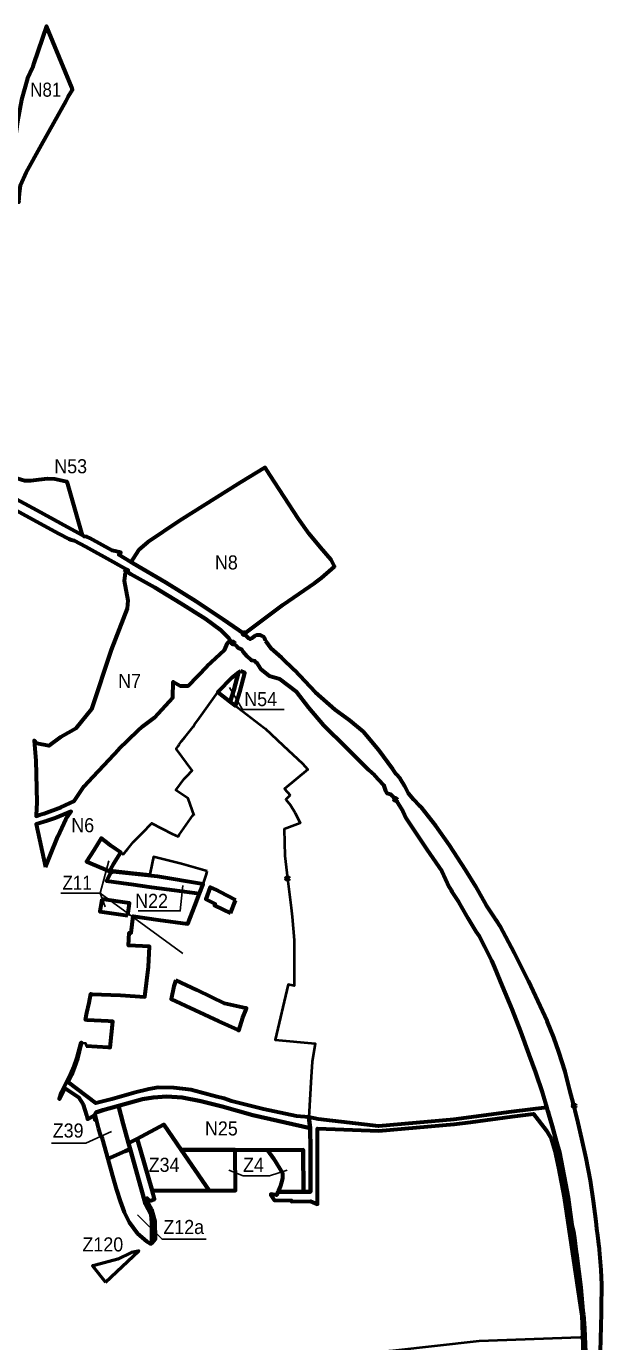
# Model space of a CAD drawing. Extents: x -650277 to -643425, y -1073980 to -1066720.
# Drawn here: x -645952 to -644970, y -1070373 to -1068130 of the extents above; entities that cross this region are included whole.
import ezdxf

# ---------------------------------------------------------------- set-up
doc = ezdxf.new("R2010")
doc.units = 0
doc.header["$LTSCALE"] = 9.6
doc.header["$PDMODE"] = 32
doc.header["$PDSIZE"] = 4.8
for name, color, linetype, lineweight in [('1', 7, 'Continuous', 60), ('11', 7, 'Continuous', 60), ('15', 7, 'Continuous', 60), ('2', 7, 'Continuous', 40), ('3', 7, 'Continuous', 60), ('40', 7, 'Continuous', 60), ('42', 7, 'Continuous', 60), ('48', 7, 'Continuous', 60), ('60', 7, 'Continuous', 60), ('63', 7, 'Continuous', 25), ('7', 7, 'Continuous', 60)]:
    doc.layers.add(name, color=color, linetype=linetype, lineweight=lineweight)

msp = doc.modelspace()

# ---------------------------------------------------------------- linework, layer by layer
at = {"layer": '1'}
msp.add_line((-645623.75, -1069825.97), (-645590.964, -1069841.09), dxfattribs=at)
at = {"layer": '1', "lineweight": 40}
msp.add_line((-645726.542, -1069939.398), (-645742.967, -1069941.862), dxfattribs=at)
for points in [[(-645668.722, -1069398.75), (-645696.19, -1069362.01), (-645692.38, -1069356.67), (-645690.81, -1069354.28), (-645687.22, -1069349), (-645680.8, -1069341.08), (-645667, -1069324.06), (-645664.89, -1069320.2), (-645658.9, -1069312.83), (-645625.11, -1069265.42), (-645604.114, -1069281.49), (-645594.94, -1069288.511)], [(-645594.94, -1069288.511), (-645583.13, -1069297.55), (-645546.19, -1069325.81), (-645544.26, -1069327.35), (-645513.41, -1069356.18), (-645480.72, -1069386.96), (-645471.738, -1069397.026), (-645511.464, -1069429.794), (-645501.878, -1069440.838)], [(-645665.58, -1069475.61), (-645675.91, -1069446.56), (-645696.45, -1069432.21), (-645682.28, -1069412.88), (-645678.06, -1069408.54), (-645668.61, -1069398.9), (-645668.722, -1069398.75)], [(-645501.878, -1069440.838), (-645508.994, -1069447.955), (-645501, -1069458), (-645493, -1069471), (-645484.783, -1069488.256), (-645512, -1069499), (-645511, -1069544), (-645506, -1069583)], [(-645786.388, -1069541.673), (-645779.376, -1069532.962), (-645778.754, -1069532.198), (-645769.369, -1069520.672), (-645768.995, -1069520.305), (-645752.715, -1069504.328), (-645738.986, -1069489.868), (-645737.897, -1069488.534), (-645702.82, -1069506.64), (-645692.87, -1069511.229), (-645690.84, -1069508.32), (-645667.31, -1069474.6), (-645665.58, -1069475.61)], [(-645836.44, -1069534.5), (-645824.05, -1069514.34), (-645811.75, -1069523.81), (-645808.1, -1069526.61), (-645799.07, -1069532.8), (-645790.62, -1069538.59), (-645786.388, -1069541.673)], [(-645810.08, -1069570.39), (-645848.78, -1069553.91), (-645836.44, -1069534.5)], [(-645643.16, -1069570.6), (-645687.29, -1069558.04), (-645734.5, -1069545.89), (-645736.8, -1069556.91), (-645741.14, -1069576.19), (-645769.04, -1069573), (-645803.513, -1069569.263), (-645810.08, -1069570.39)], [(-645676.34, -1069660.28), (-645670.23, -1069644.67), (-645664.19, -1069629.24), (-645657.52, -1069612.2), (-645656.15, -1069608.71), (-645649.91, -1069592.39), (-645648.68, -1069589.06), (-645644.56, -1069575.61), (-645643.16, -1069570.6)], [(-645506, -1069583), (-645500.137, -1069632.833), (-645500.137, -1069632.833)], [(-645500.137, -1069632.833), (-645498, -1069648), (-645495, -1069688), (-645495, -1069744), (-645495, -1069766), (-645504.976, -1069763.332), (-645527, -1069858), (-645459.312, -1069864.01), (-645464.288, -1069895.362), (-645465.756, -1069921.035), (-645469.701, -1069990.011)], [(-645839.721, -1069780.247), (-645839.658, -1069779.835), (-645791.2, -1069781.92), (-645749.48, -1069784.61), (-645743.36, -1069733.7), (-645743.01, -1069730.72), (-645741.43, -1069698.68), (-645763.24, -1069697.58), (-645777.62, -1069696.85), (-645776.45, -1069675.26), (-645773.02, -1069675.47), (-645769.36, -1069648), (-645769.264, -1069647.213), (-645726.57, -1069653.22), (-645676.34, -1069660.28)], [(-645804.185, -1069825.84), (-645804.28, -1069826.76), (-645812.18, -1069826.3), (-645847.62, -1069824.26), (-645850.63, -1069824.09), (-645848.35, -1069812.09), (-645844.57, -1069795.07), (-645841.41, -1069779.76), (-645839.658, -1069779.835), (-645839.721, -1069780.247)], [(-645742.967, -1069941.862), (-645768.424, -1069948.431), (-645833, -1069966), (-645880.431, -1069930.3), (-645874.219, -1069917.496), (-645869.262, -1069905.935), (-645863.95, -1069889.468), (-645857.289, -1069863.338), (-645857.204, -1069862.954), (-645850.92, -1069863.41), (-645849.79, -1069868.4), (-645808.84, -1069870.75), (-645808.28, -1069865.39), (-645804.185, -1069825.84)], [(-645469.701, -1069990.011), (-645490.814, -1069988.074), (-645547.4, -1069976.382), (-645614.072, -1069957.797), (-645625.979, -1069954.92), (-645670.325, -1069943.002), (-645699.889, -1069939.714), (-645726.542, -1069939.398)]]:
    msp.add_lwpolyline(points, dxfattribs=at)
at = {"layer": '1'}
for points in [[(-645836.44, -1069534.5), (-645848.78, -1069553.91), (-645810.08, -1069570.39), (-645803.07, -1069558.62), (-645790.62, -1069538.59), (-645799.07, -1069532.8), (-645808.1, -1069526.61), (-645811.75, -1069523.81), (-645824.05, -1069514.34)], [(-645639.638, -1070114.895), (-645594.733, -1070114.868), (-645595.2, -1070045.403), (-645687.31, -1070045.724)], [(-645522.587, -1070116.952), (-645478.664, -1070117.114), (-645479.429, -1070045.409), (-645540.433, -1070045.752), (-645530.3, -1070060.08), (-645514.49, -1070085.4), (-645514.56, -1070090.91), (-645514.61, -1070094.35), (-645517.02, -1070103.08), (-645518.35, -1070106.87), (-645521.73, -1070114.83)]]:
    msp.add_lwpolyline(points, close=True, dxfattribs=at)
for points in [[(-645849.79, -1069868.4), (-645811.848, -1069870.577), (-645808.84, -1069870.75), (-645804.28, -1069826.76), (-645812.18, -1069826.3), (-645847.62, -1069824.26), (-645850.63, -1069824.09), (-645848.35, -1069812.09), (-645844.57, -1069795.07), (-645841.41, -1069779.76), (-645839.658, -1069779.835), (-645791.2, -1069781.92), (-645749.48, -1069784.61), (-645743.36, -1069733.7), (-645741.43, -1069698.68), (-645777.62, -1069696.85), (-645776.45, -1069675.26), (-645773.02, -1069675.47), (-645769.264, -1069647.213), (-645726.57, -1069653.22), (-645676.34, -1069660.28), (-645664.19, -1069629.24), (-645656.15, -1069608.71)], [(-645594.58, -1069619.56), (-645621.56, -1069605.68), (-645626.95, -1069602.91), (-645638.203, -1069597.8), (-645645.715, -1069618.085), (-645629.78, -1069626.03), (-645630.93, -1069628.84), (-645603.7, -1069641.75)], [(-645823.082, -1069618.279), (-645823.13, -1069618.452), (-645825.295, -1069632.053), (-645826.133, -1069638.843), (-645826.151, -1069639.057), (-645778.45, -1069645.92)], [(-645778.45, -1069645.92), (-645775.46, -1069625.13), (-645823.082, -1069618.279)], [(-645603.7, -1069641.75), (-645594.818, -1069620.139), (-645594.58, -1069619.56)], [(-645696.517, -1069756.039), (-645700.028, -1069766.286), (-645704.355, -1069788.786), (-645623.75, -1069825.97)], [(-645578.134, -1069803.73), (-645613.84, -1069795.78), (-645635.79, -1069785.23), (-645660.57, -1069773.31), (-645696.517, -1069756.039)], [(-645590.964, -1069841.09), (-645589.23, -1069841.89), (-645582.31, -1069820.05), (-645577.52, -1069807.26), (-645576.34, -1069804.13), (-645578.134, -1069803.73)], [(-645772.853, -1070049.868), (-645774.423, -1070044.167), (-645783.063, -1070047.855), (-645812.76, -1070060.53)], [(-645737.756, -1070204.389), (-645737.624, -1070169.544), (-645738.79, -1070156.281), (-645748.62, -1070137.889), (-645772.853, -1070049.868)], [(-645812.76, -1070060.53), (-645804.52, -1070089.63), (-645797.66, -1070113.88), (-645791.72, -1070133.09), (-645784.83, -1070151.9), (-645784.83, -1070151.9)], [(-645784.83, -1070151.9), (-645776.26, -1070168.94), (-645761.78, -1070188.29), (-645746.73, -1070201.04), (-645739.12, -1070205.9), (-645737.756, -1070204.389)]]:
    msp.add_lwpolyline(points, dxfattribs=at)
at = {"layer": '1', "lineweight": 53}
msp.add_lwpolyline([(-645816.9, -1070270.96), (-645760.05, -1070217.79), (-645760.91, -1070217.98), (-645772.08, -1070220.39), (-645795.85, -1070231.81), (-645833.92, -1070241.96), (-645838.53, -1070243.19)], close=True, dxfattribs=at)
at = {"layer": '1'}
msp.add_point((-645506, -1069583), dxfattribs=at)
at = {"layer": '11'}
msp.add_lwpolyline([(-645639.638, -1070114.895), (-645687.31, -1070045.724), (-645717.36, -1070002.12), (-645762.868, -1070026.606), (-645757.215, -1070045.97), (-645737.075, -1070114.955)], close=True, dxfattribs=at)
at = {"layer": '15'}
for points in [[(-645586.39, -1069229.32), (-645589.844, -1069231.908), (-645597.738, -1069261.522), (-645604.114, -1069281.49), (-645594.94, -1069288.511), (-645587.298, -1069264.578), (-645578.713, -1069232.375)], [(-645735.532, -1069956.306), (-645712.222, -1069954.725), (-645686.147, -1069956.306), (-645654.145, -1069962.232), (-645617.403, -1069971.714), (-645565.133, -1069986.508), (-645467.472, -1070008.38), (-645469.701, -1069990.011), (-645490.814, -1069988.074), (-645547.4, -1069976.382), (-645601.753, -1069962.317), (-645614.072, -1069957.797), (-645625.979, -1069954.92), (-645670.325, -1069943.002), (-645699.889, -1069939.714), (-645726.542, -1069939.398), (-645742.967, -1069941.862), (-645768.424, -1069948.431), (-645806, -1069959), (-645833, -1069966), (-645880.431, -1069930.3), (-645874.219, -1069917.496), (-645869.262, -1069905.935), (-645863.95, -1069889.468), (-645857.289, -1069863.338), (-645857.204, -1069862.954), (-645858.78, -1069862.84), (-645865.78, -1069888.76), (-645870.89, -1069903.5), (-645876.15, -1069916.47), (-645892.09, -1069947.98), (-645895.66, -1069958.42), (-645894.25, -1069958.7), (-645885.422, -1069940.184), (-645862.782, -1069955.809), (-645854.81, -1069967.927), (-645849.1, -1069986.42), (-645847.135, -1069993.337), (-645836.64, -1069987.18), (-645834.65, -1069994.21), (-645833.32, -1069991.86), (-645835, -1069985), (-645833, -1069982), (-645821, -1069978), (-645794.679, -1069970.596), (-645753.706, -1069959.071)]]:
    msp.add_lwpolyline(points, close=True, dxfattribs=at)
for points in [[(-645061.76, -1069981.21), (-645064.052, -1069973.429), (-645124.233, -1069980.695), (-645222.809, -1069993.701), (-645350.784, -1070005.227), (-645453.852, -1069992.968), (-645469.701, -1069990.011), (-645467.472, -1070008.38), (-645467.068, -1070044.959), (-645466.96, -1070117.157), (-645478.664, -1070117.114), (-645522.587, -1070116.952), (-645524.82, -1070122.48), (-645534.63, -1070121.09), (-645534.7, -1070122.95), (-645529.17, -1070131.4), (-645499.276, -1070131.652), (-645499.142, -1070133.293), (-645466.862, -1070133.219), (-645454.881, -1070137.836), (-645455.073, -1070009.111), (-645350.591, -1070013.242), (-645221.99, -1070001.66), (-645194.003, -1069998.417), (-645123.206, -1069988.629), (-645086.484, -1069984.195), (-645065.235, -1070011.695)], [(-644997.87, -1070391.16), (-644999.47, -1070349.63), (-645001.64, -1070326.4), (-645001.81, -1070324.58), (-645002.308, -1070319.268), (-645005.98, -1070280.14), (-645013.51, -1070222.04), (-645013.77, -1070220.04), (-645016.92, -1070196.32), (-645018.56, -1070184.92), (-645021.14, -1070173.07), (-645027.49, -1070126.56), (-645032.21, -1070102.73), (-645042.27, -1070049.23), (-645047.28, -1070031.83), (-645054.73, -1070004.56), (-645060.612, -1069985.022), (-645061.76, -1069981.21)], [(-645065.235, -1070011.695), (-645056.555, -1070026.163), (-645050.293, -1070047.035), (-645043.92, -1070076.344), (-645034.122, -1070126.616), (-645004.791, -1070324.889), (-645004.523, -1070326.697)], [(-645757.215, -1070045.97), (-645762.868, -1070026.606), (-645777.143, -1070034.287), (-645772.853, -1070049.868), (-645748.62, -1070137.889)], [(-645737.63, -1070147.39), (-645747.67, -1070129.14), (-645745.29, -1070127.83), (-645744.73, -1070129), (-645743.87, -1070130.15), (-645742.67, -1070131.07), (-645741.83, -1070131.53), (-645740.89, -1070131.8), (-645739.41, -1070131.93), (-645738.41, -1070131.78), (-645737.48, -1070131.45), (-645734.77, -1070130.18), (-645732.91, -1070129.5), (-645737.075, -1070114.955), (-645757.215, -1070045.97)], [(-645748.62, -1070137.889), (-645738.79, -1070156.281), (-645737.624, -1070169.544), (-645737.756, -1070204.389)], [(-645737.756, -1070204.389), (-645731.3, -1070197.24), (-645731.94, -1070167.87), (-645737.63, -1070147.39)], [(-645004.523, -1070326.697), (-645004.434, -1070327.302), (-645001.312, -1070412.099), (-645004.327, -1070461.264), (-645014.277, -1070543.11), (-645023.048, -1070595.033), (-645039.574, -1070675.065)]]:
    msp.add_lwpolyline(points, dxfattribs=at)
at = {"layer": '2'}
msp.add_lwpolyline([(-645023.048, -1070595.033), (-645014.277, -1070543.11), (-645004.327, -1070461.264), (-645001.312, -1070412.099), (-645003.03, -1070365.427), (-645003.102, -1070365.432), (-645006.86, -1070365.38), (-645179.26, -1070371.74), (-645326.62, -1070388.32), (-645414.65, -1070395.37), (-645409.38, -1070411.41), (-645408.66, -1070414.62), (-645404.34, -1070433.93), (-645404.4, -1070435.88), (-645440.61, -1070469.53), (-645451.226, -1070466.394), (-645455.09, -1070479.21), (-645458.46, -1070478.86), (-645454.02, -1070501.52), (-645448.36, -1070563), (-645449.82, -1070592.72), (-645442.834, -1070659.455)], dxfattribs=at)
at = {"layer": '3'}
for points in [[(-645794.679, -1069970.596), (-645821, -1069978), (-645833, -1069982), (-645835, -1069985), (-645833.32, -1069991.86)], [(-645833.32, -1069991.86), (-645828.9, -1070007.76), (-645825.08, -1070021.52)], [(-645777.143, -1070034.287), (-645786.238, -1070001.251), (-645794.679, -1069970.596)], [(-645825.08, -1070021.52), (-645823.76, -1070021.67), (-645822.549, -1070025.948), (-645812.76, -1070060.53), (-645783.063, -1070047.855), (-645774.423, -1070044.167), (-645777.143, -1070034.287)]]:
    msp.add_lwpolyline(points, dxfattribs=at)
at = {"layer": '40'}
for points in [[(-645698.83, -1069602.85), (-645656.15, -1069608.71), (-645649.91, -1069592.39), (-645727.71, -1069579.61), (-645803.33, -1069571.62), (-645808.18, -1069573.7), (-645814.82, -1069586.81), (-645777.26, -1069592.07), (-645772.58, -1069592.73), (-645738.13, -1069597.46)], [(-645595.2, -1070045.403), (-645479.429, -1070045.409), (-645478.664, -1070117.114), (-645466.96, -1070117.157), (-645467.068, -1070044.959), (-645467.472, -1070008.38), (-645565.133, -1069986.508), (-645617.403, -1069971.714), (-645654.145, -1069962.232), (-645686.147, -1069956.306), (-645712.222, -1069954.725), (-645735.532, -1069956.306), (-645753.706, -1069959.071), (-645794.679, -1069970.596), (-645786.238, -1070001.251), (-645777.143, -1070034.287), (-645762.868, -1070026.606), (-645717.36, -1070002.12), (-645687.31, -1070045.724)]]:
    msp.add_lwpolyline(points, close=True, dxfattribs=at)
at = {"layer": '42'}
for points in [[(-645856.26, -1068997.79), (-645892.77, -1068977.86), (-645933.28, -1068955.74), (-645975.31, -1068932.8), (-646017.55, -1068909.75)], [(-645973.36, -1068898.93), (-645954.59, -1068904.41), (-645944.23, -1068904.13), (-645930.1, -1068902.47), (-645915.61, -1068901.02), (-645902.91, -1068901.43), (-645882.63, -1068905.88), (-645856.26, -1068997.79)]]:
    msp.add_lwpolyline(points, dxfattribs=at)
msp.add_lwpolyline([(-645604.114, -1069281.49), (-645597.738, -1069261.522), (-645589.844, -1069231.908), (-645600.55, -1069239.93), (-645625.11, -1069265.42)], close=True, dxfattribs=at)
at = {"layer": '48'}
msp.add_lwpolyline([(-645874.15, -1068234.44), (-645917.44, -1068129.99), (-645938.87, -1068193.06), (-645941.41, -1068200.54), (-645949.52, -1068218.72), (-645959.76, -1068255.23), (-645966.56, -1068292.38), (-645973.25, -1068342.08), (-645976.63, -1068393.14), (-645971.94, -1068405.38), (-645964.53, -1068429.83), (-645963.12, -1068415.21), (-645961.7, -1068400.54), (-645952.21, -1068378.95), (-645926.06, -1068332.18), (-645883.87, -1068256.88), (-645880.28, -1068250.47), (-645872.64, -1068238.08)], close=True, dxfattribs=at)
at = {"layer": '60'}
for points in [[(-645579.94, -1069165.52), (-645616.63, -1069140.8), (-645662.44, -1069109.89), (-645713.61, -1069078.06), (-645770.04, -1069045.34), (-645773.38, -1069043.46), (-645793.638, -1069031.021), (-645790.53, -1069027.19), (-645805.16, -1069023.52), (-645843.56, -1069002.41), (-645848.18, -1069000.48), (-645852.91, -1068999.62), (-645856.26, -1068997.79), (-645892.77, -1068977.86), (-645933.28, -1068955.74), (-645975.31, -1068932.8)], [(-645993.5, -1068942.1), (-645940.77, -1068970.74), (-645896.91, -1068994.75), (-645879.17, -1069004.02), (-645874.49, -1069005.73), (-645869.83, -1069006.45), (-645850.79, -1069016.84), (-645803.29, -1069042.92), (-645781.12, -1069055.29), (-645777.73, -1069057.2), (-645779.49, -1069059.92), (-645773.29, -1069063.99), (-645732.65, -1069086.82), (-645688.87, -1069113.44), (-645646.08, -1069140.37), (-645620.2, -1069159.26), (-645606.11, -1069172.98), (-645603.91, -1069176.86), (-645599, -1069181.48)], [(-645599, -1069181.48), (-645599, -1069181.48), (-645592.24, -1069187.73), (-645590.41, -1069189.45), (-645584.73, -1069191.88), (-645582.63, -1069195.88), (-645575.58, -1069203.57), (-645568.9, -1069209.87), (-645567.07, -1069210.45), (-645562.17, -1069212.02), (-645560.72, -1069214.25), (-645559.33, -1069214.54), (-645552.2, -1069225.59), (-645537.44, -1069237.41), (-645519.59, -1069242.38), (-645491.63, -1069264.25), (-645470.44, -1069291.24), (-645444.62, -1069321.35), (-645405.7, -1069360.27), (-645368.13, -1069397.37), (-645358.04, -1069406.84), (-645342.49, -1069423.06), (-645339.31, -1069433.27), (-645336.66, -1069437.47), (-645330.57, -1069438.89), (-645327.2, -1069442.53), (-645323.36, -1069445.79), (-645322.13, -1069447.96)], [(-645571.9, -1069173.43), (-645579.94, -1069165.52), (-645579.94, -1069165.52)], [(-645543.43, -1069178.39), (-645543.547, -1069177.727), (-645543.706, -1069177.053), (-645543.907, -1069176.37), (-645544.154, -1069175.682), (-645544.448, -1069174.993), (-645544.792, -1069174.308), (-645545.186, -1069173.63), (-645545.631, -1069172.966), (-645546.127, -1069172.32), (-645546.674, -1069171.699), (-645547.269, -1069171.107), (-645547.91, -1069170.551), (-645548.594, -1069170.034), (-645549.317, -1069169.563), (-645550.076, -1069169.141), (-645550.863, -1069168.772), (-645551.674, -1069168.459), (-645552.504, -1069168.203), (-645553.344, -1069168.007), (-645554.191, -1069167.87), (-645555.036, -1069167.793), (-645555.875, -1069167.772), (-645556.702, -1069167.808), (-645557.511, -1069167.896), (-645558.298, -1069168.035), (-645559.06, -1069168.219), (-645559.793, -1069168.445), (-645560.494, -1069168.709), (-645561.162, -1069169.007), (-645561.794, -1069169.334), (-645562.39, -1069169.686), (-645562.95, -1069170.06), (-645567.5, -1069173.46), (-645569.81, -1069175.03), (-645571.9, -1069173.43)], [(-645017.46, -1069970.61), (-645018.28, -1069967.49), (-645024.45, -1069944.43), (-645032.85, -1069912.07), (-645043.5, -1069878.37), (-645051.78, -1069854.2), (-645063.26, -1069825.99), (-645095.1, -1069757.62), (-645118.98, -1069710.08), (-645143.56, -1069664.05), (-645148.8, -1069656.1), (-645150.3, -1069653.84), (-645153.33, -1069649.24), (-645166.67, -1069629), (-645184.88, -1069596.58), (-645202.56, -1069568.23), (-645230.1, -1069525.98), (-645253.4, -1069493.06), (-645278.31, -1069461.33), (-645281.4, -1069458.4), (-645290.5, -1069449.03), (-645299.61, -1069437.97), (-645306.16, -1069425.55), (-645314.14, -1069412.54), (-645321.1, -1069405.21), (-645326.59, -1069396.64), (-645350.63, -1069363.98), (-645371.12, -1069339.47), (-645376.38, -1069332.65), (-645400.07, -1069313.32), (-645424.8, -1069295.24), (-645458.45, -1069265.56), (-645494.13, -1069227.63), (-645515.89, -1069206.66), (-645534.25, -1069190.56), (-645543.43, -1069178.39)], [(-645322.13, -1069447.96), (-645309.62, -1069467.79), (-645303.57, -1069480.49), (-645268.57, -1069533.23), (-645242.75, -1069570.26), (-645230.42, -1069597.39), (-645227.27, -1069602.68), (-645225.7, -1069605.32), (-645214.76, -1069622.37), (-645198.41, -1069650.49), (-645185.17, -1069673.38), (-645179.12, -1069681.3), (-645170.3, -1069698.91), (-645158.43, -1069722.61), (-645153.44, -1069734.71), (-645140.27, -1069766.68), (-645123.84, -1069805.38), (-645108.74, -1069843.58), (-645094.42, -1069882.65), (-645083.31, -1069913.37), (-645071.53, -1069948.89), (-645063.96, -1069973.73), (-645063.23, -1069976.2), (-645062.57, -1069978.46)], [(-645062.57, -1069978.46), (-645061.76, -1069981.21), (-645060.612, -1069985.022), (-645054.73, -1070004.56), (-645047.28, -1070031.83), (-645042.27, -1070049.23), (-645032.21, -1070102.73), (-645027.49, -1070126.56), (-645021.14, -1070173.07), (-645018.56, -1070184.92), (-645016.92, -1070196.32), (-645013.77, -1070220.04), (-645013.51, -1070222.04), (-645005.98, -1070280.14), (-645002.308, -1070319.268), (-645001.81, -1070324.58), (-645001.64, -1070326.4), (-644999.47, -1070349.63), (-644997.87, -1070391.16)], [(-644996.88, -1070059.73), (-645004.02, -1070026.44), (-645010.54, -1069999.3), (-645015.548, -1069978.177), (-645016.01, -1069976.23), (-645016.89, -1069972.82), (-645017.46, -1069970.61)], [(-644972.48, -1070389.15), (-644971.37, -1070345.98), (-644970.61, -1070323.44), (-644970.55, -1070321.56), (-644970.524, -1070315.358), (-644970.36, -1070275.49), (-644971.47, -1070250.14), (-644974, -1070216.2), (-644974.29, -1070213.17), (-644974.49, -1070210.98), (-644976.94, -1070191.41), (-644978.49, -1070180.05), (-644979.57, -1070167.9), (-644984.21, -1070132.81), (-644989.62, -1070097.79), (-644996.88, -1070059.73)]]:
    msp.add_lwpolyline(points, dxfattribs=at)
for p in [(-645599, -1069181.48), (-645579.94, -1069165.52), (-645322.13, -1069447.96), (-645017.46, -1069970.61)]:
    msp.add_point(p, dxfattribs=at)
at = {"layer": '63'}
for q in [(-645817, -1069631), (-645685, -1069711)]:
    msp.add_line((-645826, -1069608), q, dxfattribs=at)
for points in [[(-645512, -1069295), (-645583, -1069295), (-645605, -1069257)], [(-645893, -1069608), (-645826, -1069608), (-645811, -1069553)], [(-645761, -1069638), (-645689, -1069638), (-645685, -1069595)], [(-645909, -1070034), (-645850, -1070034), (-645806.657, -1070014.297)], [(-645606, -1070080), (-645582, -1070090), (-645537, -1070090), (-645507, -1070080)], [(-645762, -1070156), (-645720, -1070198), (-645645, -1070198)]]:
    msp.add_lwpolyline(points, dxfattribs=at)
at = {"layer": '7'}
msp.add_line((-645918.82, -1069563.81), (-645910.9, -1069543.64), dxfattribs=at)
for points in [[(-645770.04, -1069045.34), (-645713.61, -1069078.06), (-645694.447, -1069089.98), (-645662.44, -1069109.89), (-645616.63, -1069140.8), (-645579.94, -1069165.52), (-645514.08, -1069116.5), (-645459.5, -1069078.59), (-645448.49, -1069070.45), (-645426.3, -1069051.02), (-645431.85, -1069039.83), (-645449.72, -1069018.58), (-645469.5, -1068995.09), (-645487.38, -1068969.87), (-645536.63, -1068894.79), (-645544.33, -1068882.17), (-645586.28, -1068907.71), (-645690.34, -1068973.16), (-645744.65, -1069009.71), (-645760.07, -1069023.11), (-645773.38, -1069043.46)], [(-645784.69, -1069060.74), (-645783.02, -1069061.84), (-645784.52, -1069075.66), (-645778.75, -1069108.98), (-645779.685, -1069122.296), (-645806.806, -1069193.112), (-645840.644, -1069294.052), (-645867.026, -1069327.317), (-645893.291, -1069341.938), (-645913.23, -1069356.892), (-645933.792, -1069352.53), (-645938.399, -1069347.452), (-645936.046, -1069375.651), (-645935.58, -1069381.24), (-645933.97, -1069453.52), (-645934.8, -1069474.71), (-645935.05, -1069476.32), (-645928.99, -1069474.55), (-645921.13, -1069472.25), (-645892.03, -1069461.43), (-645869.91, -1069451.02), (-645853.28, -1069425.27), (-645838.17, -1069409.28), (-645819.62, -1069389.66), (-645793.63, -1069362.15), (-645761.411, -1069331.17), (-645753.58, -1069323.64), (-645733.1, -1069308.58), (-645701.62, -1069274.36), (-645701.33, -1069247.86), (-645689, -1069254.5), (-645675.82, -1069254.48), (-645643.34, -1069220.59), (-645613.9, -1069193.45), (-645608.71, -1069181.51), (-645603.91, -1069176.86), (-645606.11, -1069172.98), (-645620.2, -1069159.26), (-645646.08, -1069140.37), (-645688.87, -1069113.44), (-645732.65, -1069086.82), (-645773.29, -1069063.99), (-645779.49, -1069059.92), (-645777.73, -1069057.2), (-645781.12, -1069055.29)]]:
    msp.add_lwpolyline(points, close=True, dxfattribs=at)
msp.add_lwpolyline([(-645910.9, -1069543.64), (-645897.92, -1069511.49), (-645884.01, -1069481.56), (-645875.02, -1069468.52), (-645902.19, -1069480.13), (-645916.13, -1069484.55), (-645934.97, -1069490.31), (-645918.82, -1069563.81)], dxfattribs=at)

# ---------------------------------------------------------------- texts
at = {"layer": '1', "width": 0.95}
msp.add_text('Z120', height=24, dxfattribs=at).set_placement((-645855.898, -1070218.668))
at = {"layer": '63'}
for s, width, p in [('N81', 0.9, (-645945, -1068250)), ('N53', 0.95, (-645904, -1068892)), ('N8', 0.95, (-645630, -1069056)), ('N7', 0.95, (-645795, -1069258)), ('N54', 0.95, (-645580, -1069289)), ('N6', 0.95, (-645875, -1069504)), ('Z11', 0.9, (-645890, -1069602)), ('N22', 0.95, (-645766, -1069633)), ('Z39', 0.95, (-645906.58, -1070024.53)), ('N25', 0.95, (-645647, -1070021)), ('Z34', 0.95, (-645743, -1070083)), ('Z4', 0.95, (-645582, -1070083)), ('Z12a', 0.95, (-645718, -1070189))]:
    msp.add_text(s, height=24, dxfattribs=dict(at, width=width)).set_placement(p)

doc.saveas('drawing.dxf')
